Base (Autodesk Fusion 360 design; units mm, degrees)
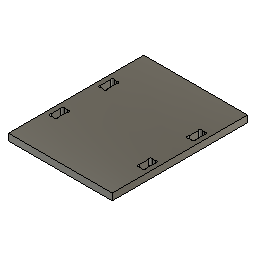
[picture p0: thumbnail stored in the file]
parameter "Length_X" = 230 (= "180 mm + Length_Z * 2 + Dis_X * 2")
parameter "Length_Y" = 300
parameter "Length_Z" = 15
parameter "Dis_Y" = 80 comment "Distance on Y-axis for the start of the Pin"
parameter "Pin" = 30 comment "Length of the Pin"
parameter "Dis_X" = 10 comment "Distance on X-axis for the Pin"
parameter "Pin_L" = 14.5 (= "Length_Z - 0.5 mm")
sketch "Sketch1" plane through (0, 0, 0) normal (0, 0, 1) x axis (1, 0, 0)
  line L1 (-230, 0) -> (0, 0)
  line L2 (-230, 300) -> (-230, 0)
  line L3 (0, 300) -> (-230, 300)
  line L4 (0, 0) -> (0, 300)
  point P1 (0, 0)
  point P2 (0, 0)
  point P4 (-230, 300)
  point P5 (0, 300)
  horizontal L1
  vertical L2
  horizontal L3
  vertical L4
  coincident P1 P2
  dimension "d4" distance P4 P5 = 230 (= "Length_X")
  dimension "d5" distance P2 P5 = 300 (= "Length_Y")
extrude "Extrude1" new body sketch "Sketch1" along normal blind 15 (= "Length_Z")
sketch "Sketch2" plane through (0, 0, 15) normal (0, 0, 1) x axis (-1, 0, 0)
  line L1 (230, -300) -> (0, -300)
  line L2 (230, 0) -> (230, -300)
  line L3 (0, 0) -> (230, 0)
  line L4 (0, -300) -> (0, 0)
  line L5 (205.5, -220) -> (220, -220)
  line L6 (205.5, -190) -> (205.5, -220)
  line L7 (220, -190) -> (205.5, -190)
  line L8 (220, -220) -> (220, -190)
  line L9 (10, -220) -> (24.5, -220)
  line L10 (10, -190) -> (10, -220)
  line L11 (24.5, -190) -> (10, -190)
  line L12 (24.5, -220) -> (24.5, -190)
  line L13 (205.5, -110) -> (220, -110)
  line L14 (205.5, -80) -> (205.5, -110)
  line L15 (220, -80) -> (205.5, -80)
  line L16 (220, -110) -> (220, -80)
  line L17 (10, -110) -> (24.5, -110)
  line L18 (10, -80) -> (10, -110)
  line L19 (24.5, -80) -> (10, -80)
  line L20 (24.5, -110) -> (24.5, -80)
  point P15 (205.5, -110)
  point P18 (24.5, -110)
  point P7 (205.5, -220)
  point P10 (24.5, -220)
  point P8 (205.5, -190)
  point P13 (24.5, -190)
  point P16 (205.5, -80)
  point P21 (24.5, -80)
  point P9 (220, -190)
  point P14 (220, -110)
  point P12 (10, -190)
  point P19 (10, -110)
  point P20 (10, -80)
  point P1 (0, 0)
  point P11 (10, -220)
  horizontal L5
  vertical L6
  horizontal L7
  vertical L8
  horizontal L9
  vertical L10
  horizontal L11
  vertical L12
  horizontal L13
  vertical L14
  horizontal L15
  vertical L16
  horizontal L17
  vertical L18
  horizontal L19
  vertical L20
  horizontal P15 P18
  horizontal P7 P10
  horizontal P8 P13
  horizontal P16 P21
  vertical P9 P14
  vertical P8 P15
  vertical P13 P18
  vertical P12 P19
  equal L10 L18
  equal L13 L17
  dimension "d10" distance P19 P20 = 30 (= "Pin")
  dimension "d12" distance P20 P21 = 14.5 (= "Pin_L")
  dimension "d13" distance P1 P20 = 80 (= "Dis_Y")
  dimension "d15" distance L1 P11 = 80 (= "Dis_Y")
  dimension "d17" distance P1 L18 = 10 (= "Dis_X")
  dimension "d18" distance L2 L16 = 10 (= "Dis_X")
extrude "Extrude2" cut sketch "Sketch2" profile of L5 L6 L7 L8 L9 L10 L11 L12 L13 L14 L15 L16 L17 L18 L19 L20 distance 15 (= "Length_Z")
base_feature "Base Feature" sketch "Sketch1" bodies "dogboneTool"
combine "Combine1" bodies "dogboneTool"
named bodies: "dogboneTool"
